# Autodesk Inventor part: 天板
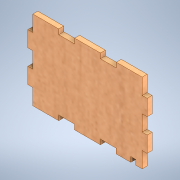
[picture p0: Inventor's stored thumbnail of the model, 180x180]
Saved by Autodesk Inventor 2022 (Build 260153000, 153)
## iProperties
Created: 2024-11
Part Number: 天板
Material: MDF 中密度繊維ボード
Document SubType Name: Modeling
Designer: shimizu
Density: 0.8 g/cm^3
Appearance: サクラ材 - ナチュラル 抑えた光沢
Author: shimizu
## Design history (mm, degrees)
sketch "スケッチ1"
  geometry: L1 (-25.119, 2.566)-(-27.619, 2.566); L2 (-27.619, 2.566)-(-27.619, -5.434); L3 (-27.619, -5.434)-(-25.119, -5.434); L4 (-25.119, -13.434)-(-27.619, -13.434); L5 (-27.619, -13.434)-(-27.619, -21.434); L6 (-27.619, -21.434)-(-25.119, -21.434); L7 (29.881, 2.566)-(32.381, 2.566); L8 (32.381, 2.566)-(32.381, -5.434); L9 (32.381, -5.434)-(29.881, -5.434); L10 (29.881, -13.434)-(32.381, -13.434); L11 (32.381, -13.434)-(32.381, -21.434); L12 (32.381, -21.434)-(29.881, -21.434); L13 (-25.119, 2.566)-(-25.119, 10.566); L14 (-25.119, -29.434)-(-25.119, -21.434); L15 (-25.119, -13.434)-(-25.119, -5.434); L16 (29.881, 10.566)-(29.881, 2.566); L17 (29.881, -5.434)-(29.881, -13.434); L18 (29.881, -21.434)-(29.881, -29.434); L19 (-4.119, -29.434)-(-4.119, -26.934); L20 (-4.119, -26.934)-(-12.119, -26.934); L21 (-12.119, -26.934)-(-12.119, -29.434); L22 (16.881, -29.434)-(16.881, -26.934); L23 (16.881, -26.934)-(8.881, -26.934); L24 (8.881, -26.934)-(8.881, -29.434); L25 (-4.119, 10.566)-(-4.119, 8.066); L26 (-4.119, 8.066)-(-12.119, 8.066); L27 (-12.119, 8.066)-(-12.119, 10.566); L28 (16.881, 10.566)-(16.881, 8.066); L29 (16.881, 8.066)-(8.881, 8.066); L30 (8.881, 8.066)-(8.881, 10.566); L31 (-25.119, 10.566)-(-12.119, 10.566); L32 (-4.119, 10.566)-(8.881, 10.566); L33 (16.881, 10.566)-(29.881, 10.566); L34 (-12.119, -29.434)-(-25.119, -29.434); L35 (29.881, -29.434)-(16.881, -29.434); L36 (8.881, -29.434)-(-4.119, -29.434); L37 (24.191, -29.434)-(26.701, -29.434); L38 (26.701, -29.434)-(26.701, -26.934); L39 (26.701, -26.934)-(24.191, -26.934); L40 (24.191, -26.934)-(24.191, -29.434); 2 further points
  constraints: 80 end point, 28 parallel, 14 perpendicular, 8 horizontal, 2 collinear, 1 point on line
  dimensions: "d29" = 55 distance between parallel lines of L17 L15; "d30" = 35 distance between parallel lines of L20 L26; "d31" = 60 distance between parallel lines of L11 L5; "d32" = 13 distance of L21.end L14.start; "d33" = 13 distance of L24.end L19.start; "d34" = 13 distance of L18.end L22.start; "d35" = 13 distance of L13.end L27.end; "d36" = 13 distance of L25.start L30.end; "d37" = 13 distance of L28.start L16.start; "d38" = 8 distance of L28.end L29.end; "d39" = 8 distance of L25.end L26.end; "d40" = 8 distance of L22.end L23.end; "d41" = 8 distance of L19.end L20.end; "d42" = 8 distance of L9.end L10.start; "d43" = 2.51 distance between parallel lines of L40 L38; "d44" = 2.5 distance between parallel lines of L37 L39; "d45" = 3.18 distance between parallel lines of L38 L18
extrude "押し出し1" new body sketch "スケッチ1" distance "d2" = 2.5; taper "d3" = 0 deg
node "ソリッド1"
